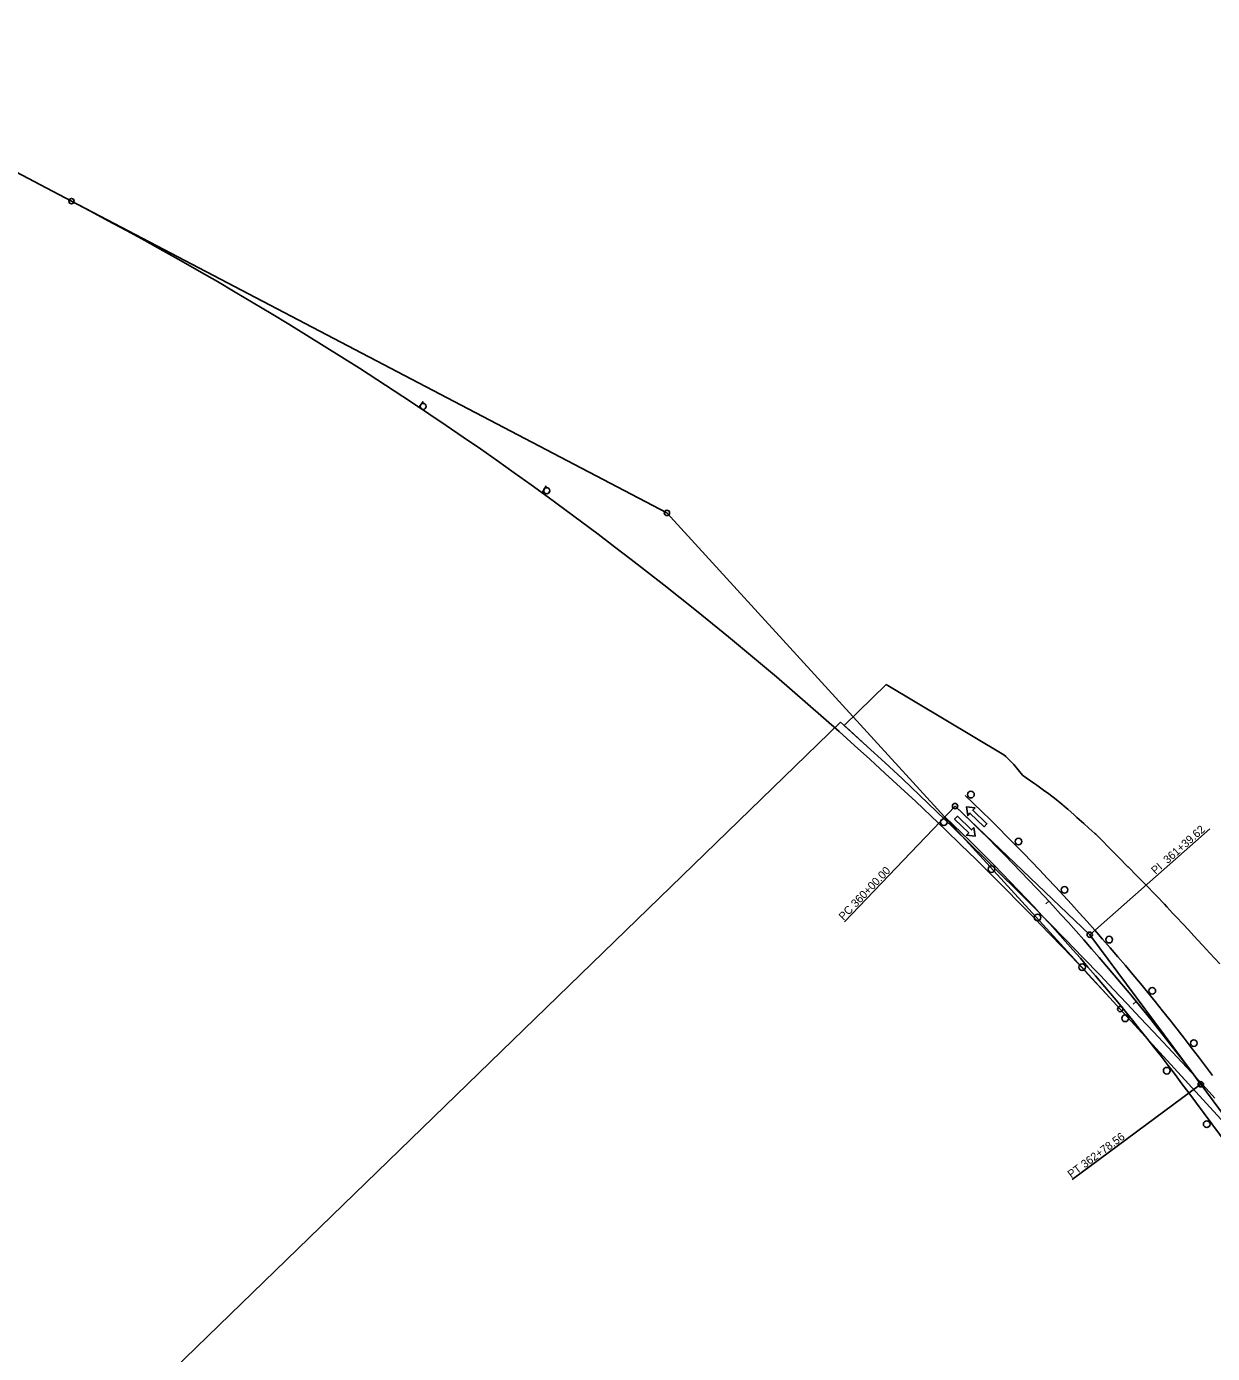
# Model space of a CAD drawing. Extents: x 1193019 to 1196816, y 1474412 to 1477212.
# Drawn here: x 1194317 to 1195206, y 1476210 to 1477205 of the extents above; entities that cross this region are included whole.
import ezdxf

# ---------------------------------------------------------------- set-up
doc = ezdxf.new("R2010")
doc.units = 0
for name, color, linetype in [('R_Draft', 7, 'Continuous'), ('R_Horz Alg', 7, 'Continuous'), ('R_Horz Alg Annot', 7, 'Continuous'), ('R_MOT', 7, 'Continuous'), ('R_No Plot', 7, 'Continuous'), ('R_Striping', 7, 'Continuous')]:
    doc.layers.add(name, color=color, linetype=linetype)

msp = doc.modelspace()

# ---------------------------------------------------------------- linework, layer by layer
at = {"layer": 'R_Draft'}
for p, q in [((1194929.71, 1476681.15), (1194961.12, 1476711.74)), ((1194961.12, 1476711.74), (1195049.47, 1476658.93))]:
    msp.add_line(p, q, dxfattribs=at)
for points in [[(1195207.63, 1476401.54), (1195198.89, 1476411.2), (1195190.15, 1476420.86), (1195175.9, 1476436.04), (1195161.65, 1476451.22), (1195151.61, 1476461.87), (1195141.57, 1476472.51), (1195131.52, 1476483.16), (1195121.48, 1476493.8), (1195108.51, 1476507.12), (1195095.54, 1476520.43), (1195082.57, 1476533.75), (1195069.6, 1476547.06), (1195058.25, 1476558.33), (1195046.91, 1476569.59), (1195035.57, 1476580.86), (1195024.22, 1476592.13), (1195011.52, 1476604.35), (1194998.83, 1476616.57), (1194986.13, 1476628.79), (1194973.44, 1476641.01), (1194960.17, 1476653.19), (1194946.9, 1476665.37), (1194929.71, 1476681.15)], [(1195049.47, 1476658.93), (1195050.78, 1476657.76), (1195053.82, 1476654.79), (1195056.86, 1476651.83), (1195063.43, 1476643.89), (1195066.02, 1476641.88), (1195071.86, 1476637.86), (1195074.08, 1476636.27), (1195079.12, 1476632.49), (1195083.02, 1476629.76), (1195088.6, 1476625.64), (1195092.8, 1476622.05), (1195096.37, 1476619.13), (1195097.31, 1476618.22), (1195102, 1476614.07), (1195104.15, 1476612.16), (1195109.39, 1476607.5), (1195113.16, 1476604.11), (1195117.61, 1476600.14), (1195118.28, 1476599.48), (1195124.31, 1476593.49), (1195126.67, 1476591.11), (1195133.16, 1476584.53), (1195135.4, 1476582.29), (1195142.38, 1476575.14), (1195142.47, 1476575.13), (1195149.64, 1476567.79), (1195152.07, 1476565.34), (1195155.49, 1476561.83), (1195156.34, 1476560.96), (1195162.65, 1476554.48), (1195163.99, 1476553.03), (1195169.72, 1476547.02), (1195171.56, 1476545.01), (1195176.15, 1476540.13), (1195178.49, 1476537.57), (1195183.74, 1476532.01), (1195187.78, 1476527.68), (1195191.82, 1476523.18), (1195194.85, 1476520.07), (1195198.29, 1476516.22), (1195203.84, 1476510.33), (1195211.19, 1476502.36)]]:
    msp.add_lwpolyline(points, dxfattribs=at)
at = {"layer": 'R_Horz Alg'}
for p, q in [((1194100.16, 1477205.24), (1194350.26, 1477074.28)), ((1195136.65, 1476468.36), (1196620.96, 1474843.25)), ((1195196.94, 1476411.99), (1195328.46, 1476234.64))]:
    msp.add_line(p, q, dxfattribs=at)
for centre, radius, start, end in [((1193021.38, 1474536.35), 2864.79, 42.40729, 62.36303), ((1193882.05, 1475436.84), 1637.02, 36.56127, 46.31104)]:
    msp.add_arc(centre, radius, start, end, dxfattribs=at)
at = {"layer": 'R_Horz Alg Annot'}
for p, q in [((1194350.26, 1477074.28), (1194796.75, 1476840.49)), ((1194796.75, 1476840.49), (1195136.65, 1476468.36)), ((1195012.81, 1476620.57), (1195113.77, 1476524.13)), ((1195113.77, 1476524.13), (1195196.94, 1476411.99))]:
    msp.add_line(p, q, dxfattribs=at)
for points in [[(1195012.81, 1476620.57), (1194929.93, 1476533.8)], [(1195113.77, 1476524.13), (1195203.74, 1476603.55)], [(1195080.77, 1476547.29), (1195082.97, 1476549.33)], [(1195146.33, 1476472.04), (1195148.65, 1476473.94)], [(1195196.94, 1476411.99), (1195100.56, 1476340.5)]]:
    msp.add_lwpolyline(points, dxfattribs=at)
for centre in [(1194350.26, 1477074.28), (1194796.75, 1476840.49), (1195012.81, 1476620.57), (1195113.77, 1476524.13), (1195136.65, 1476468.36), (1195196.94, 1476411.99)]:
    msp.add_circle(centre, 2, dxfattribs=at)
at = {"layer": 'R_MOT'}
for p, q in [((1194610.37, 1476919.33), (1194614.02, 1476924.09)), ((1194703.19, 1476855.55), (1194706.11, 1476860.79))]:
    msp.add_line(p, q, dxfattribs=at)
for centre, radius in [((1194613.98, 1476920.34), 2.25), ((1194706.62, 1476857.08), 2.25), ((1195024.7, 1476629.21), 2.5), ((1195004.41, 1476608.53), 2.5), ((1195004.41, 1476608.53), 2.5), ((1195060.35, 1476594), 2.5), ((1195040.06, 1476573.32), 2.5), ((1195094.91, 1476557.72), 2.5), ((1195074.62, 1476537.04), 2.5), ((1195128.35, 1476520.42), 2.5), ((1195108.06, 1476499.74), 2.5), ((1195160.65, 1476482.11), 2.5), ((1195140.36, 1476461.43), 2.5), ((1195191.77, 1476442.84), 2.5), ((1195171.48, 1476422.16), 2.5), ((1195201.46, 1476382.02), 2.5)]:
    msp.add_circle(centre, radius, dxfattribs=at)
at = {"layer": 'R_No Plot'}
for points in [[(1194926.99, 1476683.64), (1194028.08, 1475811.24), (1195219.02, 1474584.11), (1196092.83, 1475432.14)], [(1194926.99, 1476683.64), (1194028.08, 1475811.24), (1195219.02, 1474584.11), (1196092.83, 1475432.14)], [(1195207.63, 1476401.54), (1195198.89, 1476411.2), (1195190.15, 1476420.86), (1195175.9, 1476436.04), (1195161.65, 1476451.22), (1195151.61, 1476461.87), (1195141.57, 1476472.51), (1195131.52, 1476483.16), (1195121.48, 1476493.8), (1195108.51, 1476507.12), (1195095.54, 1476520.43), (1195082.57, 1476533.75), (1195069.6, 1476547.06), (1195058.25, 1476558.33), (1195046.91, 1476569.59), (1195035.57, 1476580.86), (1195024.22, 1476592.13), (1195011.52, 1476604.35), (1194998.83, 1476616.57), (1194986.13, 1476628.79), (1194973.44, 1476641.01), (1194960.17, 1476653.19), (1194946.9, 1476665.37), (1194933.63, 1476677.55), (1194926.99, 1476683.64)], [(1195207.63, 1476401.54), (1195198.89, 1476411.2), (1195190.15, 1476420.86), (1195175.9, 1476436.04), (1195161.65, 1476451.22), (1195151.61, 1476461.87), (1195141.57, 1476472.51), (1195131.52, 1476483.16), (1195121.48, 1476493.8), (1195108.51, 1476507.12), (1195095.54, 1476520.43), (1195082.57, 1476533.75), (1195069.6, 1476547.06), (1195058.25, 1476558.33), (1195046.91, 1476569.59), (1195035.57, 1476580.86), (1195024.22, 1476592.13), (1195011.52, 1476604.35), (1194998.83, 1476616.57), (1194986.13, 1476628.79), (1194973.44, 1476641.01), (1194960.17, 1476653.19), (1194946.9, 1476665.37), (1194933.63, 1476677.55), (1194926.99, 1476683.64)]]:
    msp.add_lwpolyline(points, dxfattribs=at)
at = {"layer": 'R_Striping'}
for p, q in [((1195188.11, 1476405.43), (1195319.63, 1476228.09)), ((1195196.94, 1476411.99), (1195328.46, 1476234.64))]:
    msp.add_line(p, q, dxfattribs=at)
for points in [[(1195026.88, 1476604.54), (1195027.86, 1476598.06), (1195021.34, 1476598.77), (1195023.07, 1476600.57), (1195012.45, 1476610.75), (1195014.53, 1476612.92), (1195025.15, 1476602.73)], [(1195027.76, 1476619.28), (1195021.24, 1476619.96), (1195022.25, 1476613.48), (1195023.97, 1476615.3), (1195034.64, 1476605.16), (1195036.7, 1476607.34), (1195026.04, 1476617.47)]]:
    msp.add_lwpolyline(points, close=True, dxfattribs=at)
for radius in [1648.02, 1626.02, 1637.02]:
    msp.add_arc((1193882.05, 1475436.84), radius, 36.56127, 46.31104, dxfattribs=at)

# ---------------------------------------------------------------- texts
at = {"layer": 'R_Horz Alg Annot'}
for s, rotation, p in [('PI  361+39.62', 41.43615, (1195163.12, 1476569.03)), ('PC 360+00.00', 46.31104, (1194929.2, 1476534.49)), ('PT 362+78.56', 36.56127, (1195099.96, 1476341.31))]:
    msp.add_text(s, height=6, rotation=rotation, dxfattribs=at).set_placement(p)

doc.saveas('drawing.dxf')
